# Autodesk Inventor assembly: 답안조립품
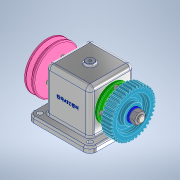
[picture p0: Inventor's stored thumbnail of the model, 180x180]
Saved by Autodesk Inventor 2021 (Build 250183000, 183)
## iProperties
Created: 2022-07
Part Number: 답안조립품
Document SubType Name: Assembly
Designer: cwnu10
Author: cwnu10
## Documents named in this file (12)
- C:\Users\cwnu10\Desktop\720706V1005\답안조립품.iam
- C:\Users\cwnu10\Desktop\720706V1005\본체.ipt
- C:\Users\cwnu10\Desktop\720706V1005\V벨트풀리.ipt
- C:\Users\cwnu10\Desktop\720706V1005\너트 M12x1.25.ipt
- C:\Users\cwnu10\Desktop\720706V1005\베어링 6204.ipt
- C:\Users\cwnu10\Desktop\720706V1005\볼트 M4x0.7.ipt
- C:\Users\cwnu10\Desktop\720706V1005\스퍼기어.ipt
- C:\Users\cwnu10\Desktop\720706V1005\오일실 20x35x8.ipt
- C:\Users\cwnu10\Desktop\720706V1005\와셔 12x24.ipt
- C:\Users\cwnu10\Desktop\720706V1005\축.ipt
- C:\Users\cwnu10\Desktop\720706V1005\커버.ipt
- C:\Users\cwnu10\Desktop\720706V1005\키 5x5.ipt
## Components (1 placed, 1 different names)
1. V벨트풀리:1
